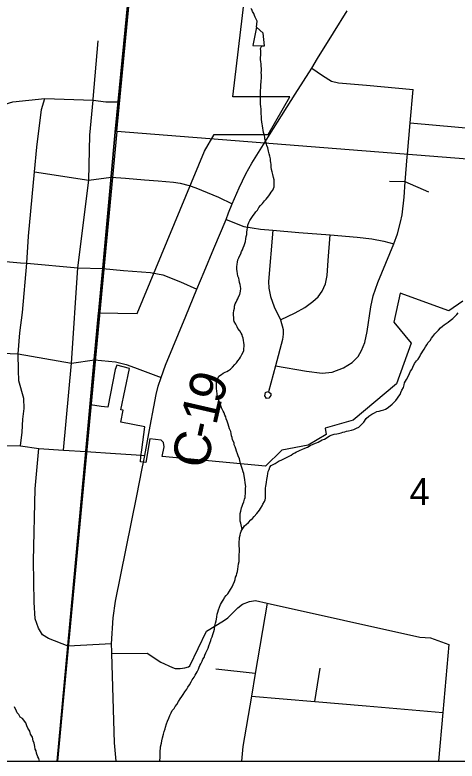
# Model space of a CAD drawing. Extents: x -7.3 to 34, y 0 to 22.
# Drawn here: x 4.11 to 4.796, y 14.1 to 15.258 of the extents above; entities that cross this region are included whole.
import ezdxf

# ---------------------------------------------------------------- set-up
doc = ezdxf.new("R2010")
doc.units = 0
for name, color, linetype in [('GM_X_City_Street', 7, 'Continuous'), ('GM_X_Corporation', 7, 'Continuous'), ('GM_X_County_Road', 7, 'Continuous'), ('GM_X_County_Road_Text', 7, 'Continuous'), ('GM_X_Minor_Lake', 7, 'Continuous'), ('GM_X_Minor_River', 7, 'Continuous'), ('GM_X_Section_Text', 7, 'Continuous'), ('GM_X_Township_Road', 7, 'Continuous'), ('SH_Data', 7, 'Continuous')]:
    doc.layers.add(name, color=color, linetype=linetype)

msp = doc.modelspace()

# ---------------------------------------------------------------- linework, layer by layer
at = {"layer": 'GM_X_City_Street'}
for p, q in [((4.2598, 14.2817), (4.1923, 14.2785)), ((4.4826, 14.2356), (4.4217, 14.2427)), ((4.5749, 14.1924), (4.5832, 14.2441))]:
    msp.add_line(p, q, dxfattribs=at)
for points in [[(4.1853, 14.5823), (4.1978, 14.7171), (4.2076, 14.865), (4.2243, 15.0012), (4.2262, 15.0709), (4.2312, 15.1254), (4.2313, 15.1269), (4.2388, 15.2174)], [(3.7475, 15.054), (3.8011, 15.0471), (3.8477, 15.0442), (3.8971, 15.0486), (3.9322, 15.0588), (3.9748, 15.0744), (4.0066, 15.0863), (4.0315, 15.0952), (4.0653, 15.1105), (4.1069, 15.1227), (4.1561, 15.1277), (4.2312, 15.1254), (4.2511, 15.1229), (4.2703, 15.1226)], [(4.1183, 14.5889), (4.121, 14.6103), (4.122, 14.6305), (4.1244, 14.6468), (4.1239, 14.6626), (4.1158, 14.69), (4.1155, 14.7063), (4.1149, 14.732), (4.1177, 14.7641), (4.1218, 14.7958), (4.1283, 14.8723), (4.1307, 14.9145), (4.1401, 15.0142), (4.1439, 15.0525), (4.1512, 15.1107), (4.1561, 15.1277)], [(4.1401, 15.0142), (4.2243, 15.0012), (4.2593, 15.006)], [(4.2593, 15.006), (4.2815, 15.0041), (4.311, 15.0017), (4.3323, 15.0001), (4.356, 14.9978), (4.3661, 14.9963), (4.3801, 14.9927), (4.3905, 14.9891)], [(3.7378, 14.9448), (3.7742, 14.9385), (3.7969, 14.9337), (3.8109, 14.9299), (3.8261, 14.9224), (3.8341, 14.9153), (3.8367, 14.9117), (3.8576, 14.8907), (3.8776, 14.8773), (3.8946, 14.8709), (3.9117, 14.8693), (3.9388, 14.8725), (3.9507, 14.8747), (3.9792, 14.8811), (3.9976, 14.8823), (4.0182, 14.8795), (4.0769, 14.8761), (4.1017, 14.8744), (4.1184, 14.873)], [(4.1184, 14.873), (4.1283, 14.8723), (4.2076, 14.865), (4.2462, 14.8639)], [(4.2462, 14.8639), (4.2781, 14.8611), (4.3204, 14.8577), (4.3392, 14.8543)], [(4.0753, 14.7351), (4.1027, 14.7324), (4.1149, 14.732), (4.1978, 14.7171), (4.2332, 14.7224)], [(4.1923, 14.2785), (4.162, 14.2899), (4.1528, 14.2959), (4.1467, 14.3063), (4.1411, 14.3207), (4.1395, 14.3463), (4.1387, 14.4104), (4.1414, 14.5222), (4.147, 14.5851)], [(4.2602, 14.267), (4.3149, 14.2675), (4.3361, 14.2535), (4.3541, 14.245), (4.3587, 14.2435), (4.3662, 14.2437), (4.3733, 14.2444), (4.3791, 14.2462), (4.381, 14.2479), (4.4073, 14.3017), (4.4334, 14.3177), (4.4401, 14.3222), (4.4555, 14.3378), (4.463, 14.3432), (4.4737, 14.3473), (4.4833, 14.349), (4.5012, 14.345), (4.7381, 14.2924), (4.7543, 14.291), (4.7827, 14.2806)], [(4.5012, 14.345), (4.4826, 14.2356), (4.4766, 14.2009), (4.4633, 14.1225), (4.4614, 14.1)], [(4.7827, 14.2806), (4.7736, 14.1752), (4.7671, 14.1)], [(4.4766, 14.2009), (4.5749, 14.1924), (4.6549, 14.1855), (4.7736, 14.1752)]]:
    msp.add_lwpolyline(points, dxfattribs=at)
at = {"layer": 'GM_X_Corporation'}
for points in [[(2.1, 20.0921), (2.1, 14.1), (4.1756, 14.1), (4.1921, 14.279), (4.2199, 14.5807), (4.233, 14.7229), (4.246, 14.8644), (4.2591, 15.0066), (4.2655, 15.0758), (4.2701, 15.1232), (4.3152, 15.5847)], [(4.3152, 15.5847), (4.2701, 15.1232), (4.2655, 15.0758), (4.2591, 15.0066), (4.246, 14.8644), (4.233, 14.7229), (4.2199, 14.5807), (4.1921, 14.279), (4.1756, 14.1), (8.9, 14.1), (8.9, 19.7858)], [(2.1, 17.0429), (2.1, 14.1), (4.1756, 14.1), (4.1921, 14.279), (4.2199, 14.5807), (4.233, 14.7229), (4.246, 14.8644), (4.2591, 15.0066), (4.2655, 15.0758), (4.2701, 15.1232), (4.3152, 15.5847)], [(4.3152, 15.5847), (4.2701, 15.1232), (4.2655, 15.0758), (4.2591, 15.0066), (4.246, 14.8644), (4.233, 14.7229), (4.2199, 14.5807), (4.1921, 14.279), (4.1756, 14.1), (8.3447, 14.1), (8.3604, 14.2653), (8.3676, 14.3403), (8.3685, 14.3492), (8.4214, 14.9056), (8.4562, 15.2161), (8.4601, 15.2687)], [(4.8045, 14.8137), (4.7828, 14.7985), (4.7074, 14.826), (4.6978, 14.7811), (4.7245, 14.7482), (4.7016, 14.6854), (4.6343, 14.6289), (4.5912, 14.6165), (4.5929, 14.6066), (4.5646, 14.5903), (4.5238, 14.5823), (4.4984, 14.5575), (4.3384, 14.5725), (4.3414, 14.5877), (4.3401, 14.5943), (4.3367, 14.598), (4.3191, 14.5998), (4.3131, 14.5634), (4.3048, 14.5641), (4.3051, 14.5725), (4.3066, 14.5829), (4.3115, 14.6187), (4.2743, 14.6258), (4.2778, 14.6444), (4.2744, 14.645), (4.2875, 14.7089), (4.2679, 14.7141), (4.2654, 14.7077), (4.2542, 14.6489), (4.2436, 14.6503), (4.2272, 14.6524), (4.233, 14.7229), (4.2397, 14.7955), (4.2994, 14.7944), (4.4037, 15.046), (4.4191, 15.0721), (4.5027, 15.0721), (4.5363, 15.1303), (4.4477, 15.1303), (4.4717, 15.3309)], [(2.1, 14.1), (5.1665, 14.1)]]:
    msp.add_lwpolyline(points, dxfattribs=at)
for points in [[(4.3675, 16.1154), (5.3843, 16.0117), (5.2968, 14.9953), (4.2681, 15.0765)], [(4.176, 14.1), (5.223, 14.1), (5.2968, 14.9953), (4.2681, 15.0765)]]:
    msp.add_lwpolyline(points, close=True, dxfattribs=at)
at = {"layer": 'GM_X_County_Road'}
msp.add_line((4.3061, 14.5744), (4.3113, 14.5741), dxfattribs=at)
for points in [[(4.3092, 14.5635), (4.3113, 14.5741), (4.3197, 14.6197), (4.3252, 14.6494), (4.3291, 14.6686), (4.3323, 14.6815), (4.3365, 14.695), (4.3437, 14.7142), (4.3749, 14.79), (4.3923, 14.832), (4.4033, 14.8588), (4.4184, 14.895), (4.4373, 14.9404), (4.4414, 14.9505), (4.447, 14.9647), (4.4576, 14.9894), (4.468, 15.0112), (4.4773, 15.0273), (4.511, 15.0813), (4.5446, 15.1346), (4.5702, 15.1749), (4.5791, 15.1901), (4.6038, 15.2299), (4.625, 15.2638)], [(3.7863, 14.6101), (3.7894, 14.6102), (3.8591, 14.6062), (3.902, 14.6025), (3.9653, 14.5979), (4.068, 14.5902), (4.1183, 14.5889), (4.147, 14.5851), (4.1853, 14.5823), (4.2201, 14.5801)], [(4.2201, 14.5801), (4.2659, 14.5772), (4.3061, 14.5744)], [(4.2671, 14.1), (4.2644, 14.1285), (4.2602, 14.267), (4.2601, 14.2695), (4.2598, 14.2817), (4.2621, 14.3223), (4.2658, 14.348), (4.2988, 14.5115), (4.3074, 14.554), (4.3092, 14.5635)]]:
    msp.add_lwpolyline(points, dxfattribs=at)
at = {"layer": 'GM_X_Minor_Lake'}
for points in [[(4.4929, 15.2096), (4.4971, 15.2094), (4.4949, 15.2292), (4.4848, 15.2385), (4.4789, 15.2102)], [(4.4789, 15.2102), (4.4929, 15.2096)]]:
    msp.add_lwpolyline(points, dxfattribs=at)
at = {"layer": 'GM_X_Minor_River'}
for points in [[(4.4848, 15.2385), (4.4854, 15.2476), (4.4843, 15.2511), (4.4825, 15.2538), (4.4814, 15.2565), (4.4804, 15.2599), (4.4785, 15.2626), (4.4771, 15.2657), (4.4756, 15.2676)], [(4.4909, 15.132), (4.4909, 15.1347), (4.491, 15.1381), (4.491, 15.1408), (4.4911, 15.1438), (4.4912, 15.1465), (4.4912, 15.1499), (4.4917, 15.1529), (4.4917, 15.1556), (4.4922, 15.159), (4.4923, 15.1624), (4.4923, 15.1651), (4.492, 15.1677), (4.4921, 15.1711), (4.4922, 15.1742), (4.4919, 15.178), (4.4916, 15.1814), (4.4912, 15.1848), (4.4909, 15.1883), (4.491, 15.1917), (4.4911, 15.1951), (4.4912, 15.1985), (4.4912, 15.2019), (4.4909, 15.2054), (4.4929, 15.2096)], [(4.4489, 14.7922), (4.449, 14.7948), (4.4495, 14.799), (4.4503, 14.8024), (4.4507, 14.8058), (4.4516, 14.8092), (4.4528, 14.8118), (4.4543, 14.8145), (4.4555, 14.8171), (4.4567, 14.8201), (4.4587, 14.8239), (4.4595, 14.8265), (4.46, 14.8292), (4.4604, 14.833), (4.4598, 14.8364), (4.4594, 14.8391), (4.4584, 14.8425), (4.4577, 14.8459), (4.457, 14.849), (4.4559, 14.8524), (4.4553, 14.8566), (4.4546, 14.8597), (4.4539, 14.8631), (4.454, 14.8665), (4.4544, 14.8711), (4.4549, 14.8737), (4.4557, 14.8775), (4.4573, 14.8809), (4.4581, 14.8835), (4.4601, 14.8869), (4.4613, 14.8903), (4.4629, 14.8929), (4.4637, 14.8963), (4.4653, 14.8997), (4.4665, 14.9027), (4.4673, 14.9061), (4.4682, 14.9099), (4.4686, 14.9137), (4.4695, 14.9171), (4.4695, 14.9198), (4.47, 14.9247), (4.4709, 14.9288), (4.4713, 14.9315), (4.4725, 14.9353), (4.4745, 14.9386), (4.4761, 14.9416), (4.4796, 14.9461), (4.4816, 14.9487), (4.4835, 14.9521), (4.4859, 14.9547), (4.4882, 14.9589), (4.4909, 14.9618), (4.494, 14.9652), (4.4968, 14.9689), (4.4995, 14.9719), (4.5015, 14.9745), (4.5038, 14.9771), (4.5057, 14.9798), (4.5073, 14.9824), (4.51, 14.9857), (4.5109, 14.9884), (4.5121, 14.991), (4.5121, 14.9948), (4.5122, 14.9982), (4.5119, 15.0017), (4.5112, 15.0055), (4.5098, 15.0097), (4.5091, 15.0139), (4.5081, 15.0177), (4.5074, 15.0215), (4.5071, 15.0257), (4.5068, 15.0287), (4.5065, 15.0314), (4.5062, 15.0341), (4.5051, 15.0386), (4.5044, 15.0421), (4.5034, 15.0459), (4.502, 15.0513), (4.5006, 15.0547), (4.4995, 15.0589), (4.4984, 15.062), (4.4977, 15.0654), (4.4974, 15.0681), (4.4964, 15.0719), (4.4957, 15.0753), (4.495, 15.0788), (4.4943, 15.0818), (4.494, 15.0852), (4.4933, 15.0883), (4.493, 15.0913), (4.4923, 15.0959), (4.4921, 15.1001), (4.4918, 15.1043), (4.4919, 15.1088), (4.4916, 15.1119), (4.4912, 15.1149), (4.491, 15.1195), (4.491, 15.1233), (4.4907, 15.126), (4.4908, 15.1294), (4.4909, 15.132)], [(4.5106, 14.5599), (4.5137, 14.5617), (4.5164, 14.5639), (4.5199, 14.5657), (4.5229, 14.5668), (4.5271, 14.569), (4.5321, 14.5715), (4.5352, 14.573), (4.5383, 14.5748), (4.541, 14.5767), (4.544, 14.5781), (4.5467, 14.5796), (4.5494, 14.5807), (4.5521, 14.5821), (4.5548, 14.5832), (4.5597, 14.5854), (4.5636, 14.5872), (4.5678, 14.5894), (4.5735, 14.5923), (4.5777, 14.5937), (4.5804, 14.5948), (4.5862, 14.5981), (4.59, 14.5995), (4.5927, 14.601), (4.5977, 14.6043), (4.6019, 14.6061), (4.6053, 14.6072), (4.6091, 14.6075), (4.6118, 14.6082), (4.616, 14.6092), (4.6187, 14.6103), (4.6214, 14.611), (4.6244, 14.6117), (4.6271, 14.6124), (4.6317, 14.6135), (4.6358, 14.6145), (4.6397, 14.6163), (4.6431, 14.6181), (4.6482, 14.6226), (4.6509, 14.6256), (4.6548, 14.6316), (4.659, 14.6349), (4.6637, 14.6382), (4.6675, 14.6404), (4.6713, 14.6422), (4.6748, 14.6429), (4.6778, 14.6436), (4.682, 14.6447), (4.6847, 14.6457), (4.6874, 14.6476), (4.692, 14.6509), (4.6951, 14.6535), (4.6974, 14.6561), (4.7006, 14.6594), (4.7033, 14.6628), (4.7056, 14.6662), (4.7076, 14.6688), (4.7084, 14.6718), (4.71, 14.6752), (4.7124, 14.6797), (4.7136, 14.6839), (4.7144, 14.6869), (4.7156, 14.6895), (4.7172, 14.6921), (4.7195, 14.6955), (4.7219, 14.7012), (4.7235, 14.7049), (4.7255, 14.7075), (4.7271, 14.7109), (4.7299, 14.7166), (4.733, 14.7207), (4.7353, 14.7237), (4.7377, 14.7278), (4.7389, 14.7304), (4.7444, 14.739), (4.7467, 14.7424), (4.7487, 14.7458), (4.7511, 14.7492), (4.7538, 14.7525), (4.7561, 14.7559), (4.7581, 14.7585), (4.7612, 14.7626), (4.7643, 14.766), (4.767, 14.7686), (4.7701, 14.7719), (4.7732, 14.7745), (4.7759, 14.7767), (4.7786, 14.7786), (4.7821, 14.7808), (4.7852, 14.7834), (4.789, 14.7867), (4.7925, 14.79), (4.7953, 14.793), (4.7976, 14.7956)], [(4.4625, 14.4595), (4.4605, 14.469), (4.4594, 14.4724), (4.4591, 14.4751), (4.4592, 14.4782), (4.4592, 14.4808), (4.4593, 14.4842), (4.4601, 14.4876), (4.4606, 14.4903), (4.4614, 14.4929), (4.4622, 14.4956), (4.4634, 14.4986), (4.465, 14.5023), (4.4662, 14.5061), (4.467, 14.5088), (4.4671, 14.5114), (4.4675, 14.5144), (4.4676, 14.5179), (4.4677, 14.5205), (4.4677, 14.5232), (4.4678, 14.5258), (4.4675, 14.5285), (4.4672, 14.5319), (4.4665, 14.5361), (4.4658, 14.5399), (4.4655, 14.5426), (4.4648, 14.546), (4.4637, 14.5487), (4.4631, 14.5525), (4.462, 14.5552), (4.4609, 14.5583), (4.4598, 14.5617), (4.4588, 14.5663), (4.4581, 14.569), (4.4563, 14.5736), (4.4552, 14.5766), (4.4534, 14.5809), (4.4524, 14.5843), (4.4517, 14.5877), (4.4502, 14.5908), (4.4499, 14.5935), (4.4474, 14.5985), (4.4467, 14.6019), (4.446, 14.6046), (4.4453, 14.6084), (4.4446, 14.6114), (4.4428, 14.6156), (4.4417, 14.6191), (4.4407, 14.6229), (4.4389, 14.6271), (4.4378, 14.631), (4.4368, 14.634), (4.4357, 14.6367), (4.4342, 14.6401), (4.4328, 14.6428), (4.4302, 14.6478), (4.4288, 14.6524), (4.4274, 14.6559), (4.4256, 14.6612), (4.4242, 14.6654), (4.4235, 14.6693), (4.4232, 14.6742), (4.4225, 14.6776), (4.4226, 14.6803), (4.4223, 14.6845), (4.4228, 14.6879), (4.4236, 14.6909), (4.4244, 14.6935), (4.4264, 14.6969), (4.4302, 14.6999), (4.4329, 14.7017), (4.436, 14.7032), (4.4387, 14.7043), (4.4414, 14.7061), (4.4441, 14.7079), (4.4475, 14.7113), (4.451, 14.715), (4.4538, 14.718), (4.4557, 14.721), (4.4581, 14.724), (4.46, 14.7266), (4.462, 14.7307), (4.464, 14.7345), (4.4648, 14.7371), (4.4652, 14.7398), (4.4653, 14.7432), (4.4654, 14.7458), (4.4651, 14.7493), (4.4644, 14.7523), (4.4637, 14.7558), (4.463, 14.7584), (4.4623, 14.7611), (4.4608, 14.7638), (4.459, 14.7676), (4.4557, 14.7711), (4.4546, 14.7738), (4.4524, 14.7777), (4.4502, 14.7819), (4.4495, 14.7846), (4.4492, 14.7876), (4.4489, 14.7922)], [(4.3783, 14.2147), (4.3807, 14.2185), (4.3834, 14.223), (4.385, 14.226), (4.3881, 14.2301), (4.3893, 14.2331), (4.3925, 14.2384), (4.3945, 14.2425), (4.3957, 14.2455), (4.3969, 14.2481), (4.3981, 14.2508), (4.4001, 14.2549), (4.4016, 14.2579), (4.4032, 14.2609), (4.4044, 14.2643), (4.406, 14.2677), (4.408, 14.2718), (4.4096, 14.2752), (4.4108, 14.279), (4.4124, 14.2831), (4.4136, 14.2869), (4.4145, 14.2896), (4.4157, 14.2929), (4.4169, 14.2963), (4.4185, 14.3009), (4.4193, 14.3046), (4.4202, 14.3099), (4.4211, 14.3137), (4.4219, 14.3175), (4.4223, 14.3202), (4.4232, 14.3239), (4.4236, 14.3281), (4.4245, 14.3311), (4.4257, 14.3345), (4.4273, 14.3387), (4.4289, 14.3428), (4.432, 14.3481), (4.434, 14.3511), (4.4352, 14.3537), (4.4375, 14.3567), (4.4403, 14.3597), (4.4426, 14.3638), (4.4442, 14.3664), (4.4466, 14.3702), (4.4485, 14.3739), (4.4505, 14.3784), (4.4517, 14.3818), (4.4522, 14.3852), (4.4534, 14.3879), (4.4542, 14.3909), (4.455, 14.3939), (4.4559, 14.3977), (4.4564, 14.4019), (4.4568, 14.406), (4.4577, 14.4098), (4.4577, 14.4128), (4.4578, 14.4166), (4.4579, 14.4208), (4.4584, 14.4242), (4.4581, 14.4292), (4.4578, 14.4341), (4.4579, 14.4368), (4.4576, 14.4406), (4.458, 14.4436), (4.4581, 14.447), (4.4593, 14.4504), (4.4598, 14.4534), (4.461, 14.4565), (4.4625, 14.4595), (4.4645, 14.4621), (4.4661, 14.4647), (4.4688, 14.4669), (4.4723, 14.4703), (4.4758, 14.474), (4.4785, 14.4762), (4.4812, 14.4792), (4.4851, 14.484), (4.487, 14.4867), (4.489, 14.4893), (4.4909, 14.4919), (4.4933, 14.496), (4.4945, 14.4987), (4.4969, 14.5028), (4.4981, 14.5054), (4.4985, 14.5081), (4.4986, 14.5111), (4.4983, 14.5142), (4.4983, 14.518), (4.4988, 14.5233), (4.4993, 14.5267), (4.4997, 14.5293), (4.5002, 14.5327), (4.5006, 14.5369), (4.5011, 14.5395), (4.5015, 14.5422), (4.502, 14.546), (4.5028, 14.549), (4.504, 14.5524), (4.5052, 14.5558), (4.5076, 14.5584), (4.5106, 14.5599)], [(4.335, 14.1), (4.3349, 14.1013), (4.3353, 14.1051), (4.3351, 14.1101), (4.3351, 14.1131), (4.3352, 14.1161), (4.3357, 14.1195), (4.3357, 14.1222), (4.3374, 14.1279), (4.3378, 14.1313), (4.339, 14.1358), (4.3403, 14.1419), (4.3412, 14.146), (4.3428, 14.1502), (4.3432, 14.1528), (4.3452, 14.1577), (4.3468, 14.1619), (4.3488, 14.1667), (4.3504, 14.1705), (4.3524, 14.1746), (4.354, 14.1784), (4.3567, 14.1814), (4.3587, 14.1848), (4.361, 14.1878), (4.3634, 14.1923), (4.3662, 14.1968), (4.3689, 14.2001), (4.3709, 14.2031), (4.3736, 14.2072), (4.3763, 14.2114), (4.3783, 14.2147)], [(4.1482, 14.1), (4.1471, 14.1039), (4.1456, 14.1065), (4.1433, 14.1122), (4.1426, 14.1157), (4.1415, 14.1187), (4.1408, 14.1225), (4.1397, 14.1278), (4.1382, 14.1316), (4.1371, 14.1369), (4.1341, 14.1419), (4.133, 14.1465), (4.13, 14.151), (4.1285, 14.1545), (4.1267, 14.1594), (4.1214, 14.1659), (4.118, 14.1682), (4.1158, 14.172), (4.1135, 14.1747), (4.1124, 14.1774), (4.1091, 14.1842)]]:
    msp.add_lwpolyline(points, dxfattribs=at)
at = {"layer": 'GM_X_Township_Road'}
for points in [[(4.5702, 15.1749), (4.587, 15.1633), (4.6011, 15.1548), (4.612, 15.1521), (4.6553, 15.1485), (4.7274, 15.142)], [(4.7189, 15.0416), (4.7229, 15.0899), (4.7274, 15.142)], [(4.7229, 15.0899), (4.7979, 15.0833), (4.8907, 15.075)], [(4.5143, 14.713), (4.5621, 14.7051), (4.5866, 14.7017), (4.602, 14.7033), (4.6197, 14.7099), (4.6332, 14.7185), (4.6421, 14.7277), (4.6477, 14.7371), (4.6524, 14.7493), (4.6563, 14.7662), (4.662, 14.8046), (4.6656, 14.8215), (4.6729, 14.8424), (4.6974, 14.9022), (4.7033, 14.9177), (4.708, 14.936), (4.7105, 14.9476), (4.7136, 14.9746), (4.7154, 14.9984), (4.7185, 15.0376), (4.7189, 15.0416)], [(4.752, 14.9823), (4.7154, 14.9984), (4.691, 14.9991)], [(4.3905, 14.9891), (4.4256, 14.975), (4.447, 14.9647)], [(4.4373, 14.9404), (4.4647, 14.9292), (4.4908, 14.925), (4.5097, 14.9234), (4.5501, 14.9201), (4.5988, 14.9166), (4.6406, 14.9128), (4.6634, 14.9104), (4.6822, 14.9067), (4.6974, 14.9022)], [(4.5097, 14.9234), (4.503, 14.8441), (4.5039, 14.8334), (4.5064, 14.8206), (4.512, 14.8049), (4.5216, 14.7846), (4.5257, 14.7697), (4.5258, 14.7623), (4.5249, 14.7539), (4.5143, 14.713), (4.5034, 14.6727), (4.5066, 14.6704), (4.5066, 14.6672), (4.5038, 14.6631), (4.4999, 14.6627), (4.4975, 14.6667), (4.4987, 14.6717), (4.5024, 14.6734)], [(4.5216, 14.7846), (4.5447, 14.7955), (4.5595, 14.8037), (4.5721, 14.8127), (4.58, 14.8202), (4.5867, 14.8288), (4.5917, 14.8404), (4.594, 14.8531), (4.5959, 14.8763), (4.5988, 14.9166)], [(4.3392, 14.8543), (4.3669, 14.8434), (4.3923, 14.832)], [(4.2332, 14.7224), (4.266, 14.7191), (4.2823, 14.7152), (4.2956, 14.7108), (4.3365, 14.695)]]:
    msp.add_lwpolyline(points, dxfattribs=at)
at = {"layer": 'SH_Data'}
msp.add_line((2.1, 14.1), (8.9, 14.1), dxfattribs=at)

# ---------------------------------------------------------------- texts
at = {"layer": 'GM_X_County_Road_Text'}
for s, rotation, p in [('9', 71.4202, (4.4294, 14.6523)), ('1', 77.0569, (4.422, 14.6196)), ('-', 77.8802, (4.4171, 14.597)), ('C', 78.0249, (4.4075, 14.5514))]:
    msp.add_text(s, height=0.0568, rotation=rotation, dxfattribs=at).set_placement(p)
at = {"layer": 'GM_X_Section_Text'}
msp.add_text('4', height=0.0419, rotation=0, dxfattribs=at).set_placement((4.7221, 14.4971))

doc.saveas('drawing.dxf')
